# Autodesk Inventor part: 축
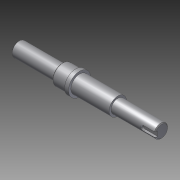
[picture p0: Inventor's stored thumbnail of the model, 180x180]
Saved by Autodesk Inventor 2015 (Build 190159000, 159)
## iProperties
Company: 한국ATC센터
Created: 2014-03
Part Number: 축
Document SubType Name: Modeling
Designer: KYOUNG IL JANG
Density: 1 g/cm^3
Material: 일반
Appearance: Default
Author: KYOUNG IL JANG
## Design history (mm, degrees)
sketch "스케치1"
  geometry: L1 (-102, 80)-(78, 80); L2 (-30.3, 106)-(-30.3, 54) reference; L3 (23, 99.7)-(23, 60.3) reference; L4 (-102, 80)-(-102, 89); L5 (-102, 89)-(-47, 89); L6 (-47, 89)-(-47, 92.5); L7 (-47, 92.5)-(-30, 92.5); L8 (-25, 94)-(-25, 91); L9 (-25, 91)-(23, 91); L10 (23, 91)-(23, 88.5); L11 (23, 88.5)-(78, 88.5); L12 (78, 88.5)-(78, 80); L13 (-30, 94)-(-25, 94); L14 (-31, 92.5)-(-44, 92.5) reference; L15 (-30, 105)-(-30, 55) reference; L16 (-30, 94)-(-30, 92.5); L17 (-68, 65.3)-(-68, 94.7) reference; L18 (-96, 89)-(-96, 85.5); L19 (-96, 85.5)-(-74, 85.5); L20 (-74, 85.5)-(-74, 89); L21 (60, 75)-(83, 75); L22 (83, 75)-(83, 71.5); L23 (83, 71.5)-(60, 71.5); L24 (60, 71.5)-(60, 75); 2 further points
  constraints: 40 end point, 12 perpendicular, 7 point on line, 3 horizontal, 3 parallel, 2 collinear, 1 midpoint, 1 other
  dimensions: "d0" = 18 diameter of L5 L1; "d1" = 17 distance of L6.end L7.end; "d2" = 5 distance of L13.start L8.start; "d3" = 28 diameter of L13 L1; "d4" = 22 diameter of L9 L1; "d5" = 17 diameter of L11 L1; "d8" = 34 distance between parallel lines of L17 L4; "d9" = 55 distance of L10.end L11.end; "d11" = 3.5 distance between parallel lines of L19 L5; "d12" = 22 distance between parallel lines of L20 L18; "d13" = 6 distance between parallel lines of L18 L4; "d14" = 17 diameter of L23 L1 (= d5); "d15" = 3.5 distance of L23.end L21.start (= d11); "d16" = 18 distance between parallel lines of L24 L12; "d17" = 23 distance of L22.end L23.end
  node "참조1"
  node "참조2"
  node "참조3"
  node "참조4"
revolve "회전1" stored, may be unused: angle "d10" = 90 deg
extrude "돌출1" cut sketch "스케치1" stored distance "d18" = 6; taper "d19" = 0 deg
fillet "모깎기1" dims "d20" = 3
chamfer "모따기1" distance "d21" = 1; stored, may be unused: second distance "d22" = 2, angle "d23" = 45 deg
node "솔리드1"
